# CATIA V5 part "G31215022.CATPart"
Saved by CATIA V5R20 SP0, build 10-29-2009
Part number: G31215022
Revision: 10
Definition: design
Nomenclature: G31215022
Source: made
Description: NOT SPECIFIED
Bounding box of the stored display mesh (mm): x -6 to 22, y -12.31 to 12.31, z -12.5 to 12.5
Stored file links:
  C:\Users\Raffaele\Desktop\3D X SITO CF\BOLEX\23-BUSH REF 312\G31215022.CATPart

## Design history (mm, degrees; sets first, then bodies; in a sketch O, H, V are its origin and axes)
Body1 "MANIFOLD_SOLID_BREP #5573" (main body)
  Solid1: solid without history
Body2 "MANIFOLD_SOLID_BREP #5716"
  Solid2: solid without history
Body3 "MANIFOLD_SOLID_BREP #5859"
  Solid3: solid without history
Body4 "MANIFOLD_SOLID_BREP #6002"
  Solid4: solid without history
Body5 "MANIFOLD_SOLID_BREP #6145"
  Solid5: solid without history
Body6 "MANIFOLD_SOLID_BREP #6290"
  Solid6: solid without history
Body7 "MANIFOLD_SOLID_BREP #6435"
  Solid7: solid without history
Body8 "MANIFOLD_SOLID_BREP #6580"
  Solid8: solid without history
Body9 "MANIFOLD_SOLID_BREP #6725"
  Solid9: solid without history
Body10 "MANIFOLD_SOLID_BREP #6870"
  Solid10: solid without history
Body11 "MANIFOLD_SOLID_BREP #7015"
  Solid11: solid without history
Body12 "MANIFOLD_SOLID_BREP #7160"
  Solid12: solid without history
Body13 "MANIFOLD_SOLID_BREP #7305"
  Solid13: solid without history
Body14 "MANIFOLD_SOLID_BREP #7450"
  Solid14: solid without history
Body15 "MANIFOLD_SOLID_BREP #7595"
  Solid15: solid without history
Body16 "MANIFOLD_SOLID_BREP #7740"
  Solid16: solid without history
Body17 "MANIFOLD_SOLID_BREP #7885"
  Solid17: solid without history
Body18 "MANIFOLD_SOLID_BREP #8030"
  Solid18: solid without history
Body19 "MANIFOLD_SOLID_BREP #8175"
  Solid19: solid without history
Body20 "MANIFOLD_SOLID_BREP #8319"
  Solid20: solid without history
Body21 "MANIFOLD_SOLID_BREP #8462"
  Solid21: solid without history
Body22 "MANIFOLD_SOLID_BREP #8607"
  Solid22: solid without history
Body23 "MANIFOLD_SOLID_BREP #8751"
  Solid23: solid without history
Body24 "MANIFOLD_SOLID_BREP #8894"
  Solid24: solid without history
Body25 "MANIFOLD_SOLID_BREP #9039"
  Solid25: solid without history
Body26 "MANIFOLD_SOLID_BREP #9184"
  Solid26: solid without history
Body27 "MANIFOLD_SOLID_BREP #9329"
  Solid27: solid without history
Body28 "MANIFOLD_SOLID_BREP #9474"
  Solid28: solid without history
Body29 "MANIFOLD_SOLID_BREP #9619"
  Solid29: solid without history
Body30 "MANIFOLD_SOLID_BREP #9764"
  Solid30: solid without history
Body31 "MANIFOLD_SOLID_BREP #9909"
  Solid31: solid without history
Body32 "MANIFOLD_SOLID_BREP #10052"
  Solid32: solid without history
Body33 "MANIFOLD_SOLID_BREP #10195"
  Solid33: solid without history
Body34 "MANIFOLD_SOLID_BREP #10340"
  Solid34: solid without history
Body35 "MANIFOLD_SOLID_BREP #10485"
  Solid35: solid without history
Body36 "MANIFOLD_SOLID_BREP #10629"
  Solid36: solid without history
Body37 "MANIFOLD_SOLID_BREP #10772"
  Solid37: solid without history
Body38 "MANIFOLD_SOLID_BREP #10917"
  Solid38: solid without history
Body39 "MANIFOLD_SOLID_BREP #11061"
  Solid39: solid without history
Body40 "MANIFOLD_SOLID_BREP #11204"
  Solid40: solid without history
Body41 "MANIFOLD_SOLID_BREP #11349"
  Solid41: solid without history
